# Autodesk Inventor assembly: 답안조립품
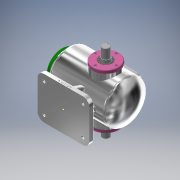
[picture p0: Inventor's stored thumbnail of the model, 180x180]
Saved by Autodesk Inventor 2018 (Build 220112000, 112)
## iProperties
Created: 2021-11
Part Number: 답안조립품
Material: 일반
Document SubType Name: Assembly
Designer: na
Author: na
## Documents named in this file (11)
- C:\Users\na\Desktop\711106V1038\답안조립품.iam
- C:\Users\na\Desktop\711106V1038\본체.ipt
- C:\Users\na\Desktop\711106V1038\베어링 6205.ipt
- 베어링 6205.ipt
- C:\Users\na\Desktop\711106V1038\축 커버.ipt
- C:\Users\na\Desktop\711106V1038\볼트 M4x0.7.ipt
- C:\Users\na\Desktop\711106V1038\오일실.ipt
- 오일실.ipt
- C:\Users\na\Desktop\711106V1038\편심축.ipt
- C:\Users\na\Desktop\711106V1038\슬라이드 커버.ipt
- C:\Users\na\Desktop\711106V1038\부시.ipt
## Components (12 placed, 1 different names)
1. M4x0.7:1
2. M4x0.7:2
3. M4x0.7:3
4. M4x0.7:4
5. M4x0.7:5
6. M4x0.7:6
7. M4x0.7:7
8. M4x0.7:8
9. M4x0.7:9
10. M4x0.7:10
11. M4x0.7:11
12. M4x0.7:12
